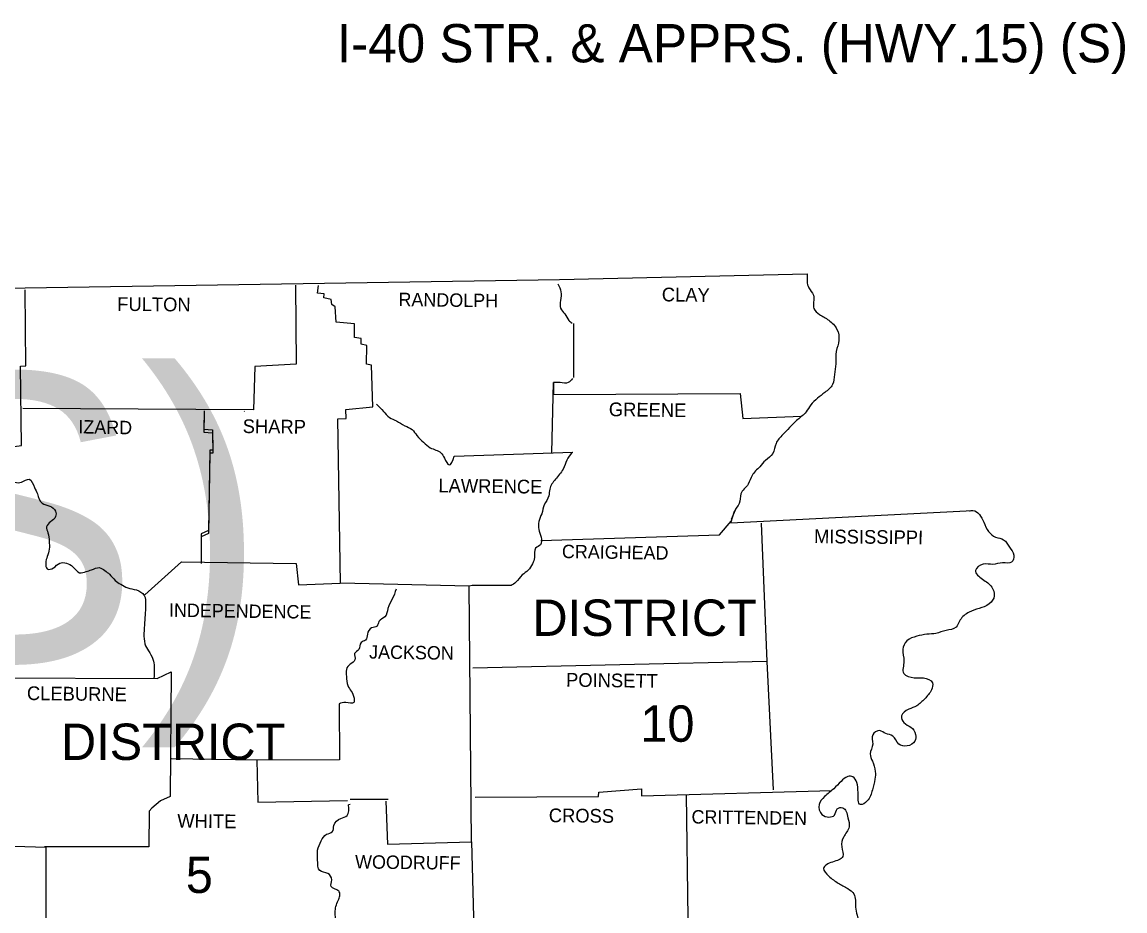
# Model space of a CAD drawing. Extents: x 1127717 to 1741049, y 2026793 to 2244711.
# Drawn here: x 1371845 to 1389121, y 2139792 to 2153727 of the extents above; entities that cross this region are included whole.
import ezdxf

# ---------------------------------------------------------------- set-up
doc = ezdxf.new("R2010")
doc.units = 0
doc.layers.add('1', color=7, linetype='Continuous')
doc.layers.add('R_Draft', color=7, linetype='Continuous')

msp = doc.modelspace()

# ---------------------------------------------------------------- linework, layer by layer
at = {"layer": 'R_Draft'}
for p, q in [((1380455, 2146979), (1380470, 2146984)), ((1382945, 2145874), (1383005, 2146059)), ((1382960, 2145934), (1383020, 2146079)), ((1376985, 2141544), (1377580, 2141544))]:
    msp.add_line(p, q, dxfattribs=at)
for points in [[(1356715, 2149549), (1364800, 2149544), (1371895, 2149559), (1380265, 2149689), (1384145, 2149779)], [(1370380, 2137464), (1371505, 2137469), (1371555, 2138059), (1372225, 2138109), (1372225, 2140789), (1371375, 2140814), (1371390, 2143449), (1370320, 2143519), (1370305, 2144699), (1370270, 2144759), (1370300, 2145499), (1370920, 2145519), (1370945, 2146129), (1371625, 2146154), (1371635, 2146549), (1371515, 2146704), (1371485, 2147039), (1371835, 2147089), (1371820, 2148334), (1371905, 2148339), (1371895, 2149529)], [(1376130, 2149604), (1376140, 2148364), (1375490, 2148329), (1375470, 2147649), (1371855, 2147669)], [(1377545, 2141514), (1377570, 2140839), (1378885, 2140874), (1378850, 2144884), (1376835, 2144929), (1376790, 2147509), (1376920, 2147514), (1376915, 2147654), (1377340, 2147694), (1377320, 2148349), (1377240, 2148364), (1377245, 2148654), (1377155, 2148679), (1377155, 2148764), (1377050, 2148779), (1377050, 2148994), (1376765, 2149024), (1376750, 2149264), (1376695, 2149299), (1376685, 2149379), (1376570, 2149404), (1376575, 2149464), (1376475, 2149479), (1376490, 2149599)], [(1380485, 2148999), (1380485, 2148154)], [(1380143, 2146973), (1380170, 2148074), (1380170, 2147889), (1383095, 2147904), (1383135, 2147514), (1384053, 2147548)], [(1374700, 2147634), (1374690, 2147344), (1374830, 2147334), (1374835, 2147014), (1374785, 2147014), (1374765, 2145754), (1374650, 2145704), (1374650, 2145284)], [(1375325, 2147624), (1375330, 2147629)], [(1374700, 2147589), (1374690, 2147299), (1374830, 2147289), (1374835, 2146969), (1374785, 2146969), (1374765, 2145709), (1374650, 2145659), (1374650, 2145239)], [(1378615, 2146919), (1380470, 2146984)], [(1382945, 2145874), (1386740, 2146069)], [(1379970, 2145599), (1382770, 2145689), (1382953, 2145901)], [(1383425, 2145869), (1383510, 2143704), (1383610, 2141689)], [(1373770, 2144749), (1374340, 2145264), (1376140, 2145239), (1376175, 2144904), (1376830, 2144929)], [(1379505, 2144894), (1378895, 2144894), (1378850, 2144884)], [(1383510, 2143704), (1378905, 2143599)], [(1371390, 2143449), (1373960, 2143434), (1374180, 2143539), (1374165, 2141584), (1374015, 2141519), (1373880, 2141404), (1373835, 2141359), (1373830, 2140799), (1372195, 2140799)], [(1376810, 2143039), (1376820, 2142159), (1375520, 2142154), (1374185, 2142179)], [(1375520, 2142154), (1375540, 2141499), (1376945, 2141524)], [(1378945, 2141574), (1380875, 2141584), (1380880, 2141654), (1381550, 2141704), (1381550, 2141599), (1384528, 2141681)], [(1382249, 2141619), (1382275, 2139674), (1382320, 2139644), (1382336, 2139368)], [(1376985, 2141459), (1376960, 2141454)], [(1378885, 2140874), (1378960, 2138134), (1377770, 2138129), (1377765, 2138019), (1377420, 2137999), (1377390, 2137429), (1376970, 2137429)]]:
    msp.add_lwpolyline(points, dxfattribs=at)
for points in [[(1384145, 2149779), (1384170, 2149559), (1384240, 2149444), (1384250, 2149234), (1384335, 2149144), (1384480, 2149054), (1384610, 2148909), (1384640, 2148739), (1384600, 2148564), (1384590, 2148369), (1384570, 2148199), (1384540, 2148044), (1384420, 2147919), (1384305, 2147829), (1384200, 2147724), (1384125, 2147614), (1383995, 2147494), (1383865, 2147369), (1383760, 2147259), (1383655, 2147119), (1383605, 2146964), (1383490, 2146854), (1383400, 2146754), (1383280, 2146619), (1383220, 2146484), (1383105, 2146329), (1383080, 2146179), (1383005, 2146059), (1383000, 2146039)], [(1384145, 2149779), (1384170, 2149559), (1384240, 2149444), (1384250, 2149234), (1384335, 2149144), (1384480, 2149054), (1384610, 2148909), (1384640, 2148739), (1384600, 2148564), (1384590, 2148369), (1384570, 2148199), (1384540, 2148044), (1384420, 2147919), (1384305, 2147829), (1384200, 2147724), (1384125, 2147614), (1383995, 2147494), (1383865, 2147369), (1383760, 2147259), (1383655, 2147119), (1383605, 2146964), (1383490, 2146854), (1383400, 2146754), (1383280, 2146619), (1383220, 2146484), (1383105, 2146329), (1383080, 2146179), (1383005, 2146059), (1383000, 2146039)], [(1380240, 2149624), (1380285, 2149499), (1380280, 2149364), (1380280, 2149239), (1380345, 2149154), (1380410, 2149049), (1380460, 2149004)], [(1380465, 2148139), (1380400, 2148074), (1380275, 2148074), (1380170, 2148074)], [(1377395, 2147739), (1377505, 2147624), (1377600, 2147529), (1377710, 2147474), (1377840, 2147399), (1377955, 2147339), (1378030, 2147244), (1378135, 2147139), (1378240, 2147054), (1378405, 2146974), (1378460, 2146889), (1378535, 2146784), (1378615, 2146919)], [(1380455, 2146979), (1380380, 2146859), (1380320, 2146719), (1380200, 2146559), (1380110, 2146404), (1380095, 2146299), (1380025, 2146159), (1379985, 2146019), (1379940, 2145899), (1379940, 2145774), (1379975, 2145649), (1379965, 2145534), (1379890, 2145479), (1379870, 2145334), (1379840, 2145234), (1379775, 2145134), (1379680, 2145059), (1379580, 2144944), (1379505, 2144894)], [(1371635, 2146549), (1371835, 2146514), (1371955, 2146559), (1372040, 2146429), (1372085, 2146329), (1372160, 2146184), (1372280, 2146139), (1372370, 2146059), (1372370, 2145974), (1372290, 2145894), (1372230, 2145814), (1372250, 2145719), (1372270, 2145589), (1372270, 2145464), (1372240, 2145349), (1372215, 2145244), (1372240, 2145154), (1372335, 2145169), (1372435, 2145244), (1372540, 2145244), (1372640, 2145189), (1372745, 2145094), (1372850, 2145114), (1372935, 2145139), (1373055, 2145174), (1373140, 2145129), (1373215, 2145069), (1373305, 2144974), (1373390, 2144914), (1373500, 2144859), (1373635, 2144824), (1373760, 2144739), (1373780, 2144594), (1373775, 2144469), (1373765, 2144314), (1373755, 2144144), (1373770, 2143979), (1373825, 2143869), (1373895, 2143739), (1373915, 2143619), (1373910, 2143429)], [(1386685, 2146064), (1386740, 2146069), (1386910, 2145889), (1386985, 2145739), (1387095, 2145654), (1387220, 2145609), (1387315, 2145494), (1387380, 2145369), (1387345, 2145259), (1387205, 2145249), (1387050, 2145224), (1386900, 2145229), (1386780, 2145129), (1386890, 2144994), (1387035, 2144869), (1387075, 2144734), (1386995, 2144604), (1386835, 2144534), (1386680, 2144474), (1386540, 2144354), (1386475, 2144239), (1386320, 2144189), (1386160, 2144144), (1386020, 2144129), (1385860, 2144099), (1385705, 2144024), (1385640, 2143894), (1385660, 2143709), (1385655, 2143514), (1385820, 2143449), (1385965, 2143444), (1386105, 2143369), (1386090, 2143259), (1385985, 2143119), (1385860, 2143009), (1385735, 2142954), (1385620, 2142849), (1385660, 2142744), (1385765, 2142674), (1385840, 2142559), (1385830, 2142454), (1385710, 2142379), (1385580, 2142409), (1385485, 2142534), (1385375, 2142574), (1385280, 2142619), (1385170, 2142554), (1385170, 2142409), (1385130, 2142254), (1385165, 2142139), (1385210, 2141979), (1385205, 2141859), (1385165, 2141689), (1385080, 2141514), (1384980, 2141459), (1384940, 2141649), (1384920, 2141804), (1384860, 2141894), (1384780, 2141899), (1384675, 2141824), (1384560, 2141709), (1384415, 2141584), (1384330, 2141459), (1384375, 2141304), (1384485, 2141264), (1384570, 2141294), (1384615, 2141394), (1384700, 2141409), (1384780, 2141254)], [(1386685, 2146064), (1386740, 2146069), (1386910, 2145889), (1386985, 2145739), (1387095, 2145654), (1387220, 2145609), (1387315, 2145494), (1387380, 2145369), (1387345, 2145259), (1387205, 2145249), (1387050, 2145224), (1386900, 2145229), (1386780, 2145129), (1386890, 2144994), (1387035, 2144869), (1387075, 2144734), (1386995, 2144604), (1386835, 2144534), (1386680, 2144474), (1386540, 2144354), (1386475, 2144239), (1386320, 2144189), (1386160, 2144144), (1386020, 2144129), (1385860, 2144099), (1385705, 2144024), (1385640, 2143894), (1385660, 2143709), (1385655, 2143514), (1385820, 2143449), (1385965, 2143444), (1386105, 2143369), (1386090, 2143259), (1385985, 2143119), (1385860, 2143009), (1385735, 2142954), (1385620, 2142849), (1385660, 2142744), (1385765, 2142674), (1385840, 2142559), (1385830, 2142454), (1385710, 2142379), (1385580, 2142409), (1385485, 2142534), (1385375, 2142574), (1385280, 2142619), (1385170, 2142554), (1385170, 2142409), (1385130, 2142254), (1385165, 2142139), (1385210, 2141979), (1385205, 2141859), (1385165, 2141689), (1385080, 2141514), (1384980, 2141459), (1384940, 2141649), (1384920, 2141804), (1384860, 2141894), (1384780, 2141899), (1384675, 2141824), (1384560, 2141709), (1384415, 2141584), (1384330, 2141459), (1384375, 2141304), (1384485, 2141264), (1384570, 2141294), (1384615, 2141394), (1384700, 2141409), (1384780, 2141254)], [(1377705, 2144839), (1377645, 2144684), (1377575, 2144534), (1377530, 2144404), (1377435, 2144329), (1377405, 2144259), (1377320, 2144229), (1377255, 2144129), (1377225, 2144039), (1377155, 2143999), (1377120, 2143889), (1377055, 2143829), (1377060, 2143729), (1376985, 2143659), (1376925, 2143579), (1376925, 2143469), (1376950, 2143324), (1377000, 2143239), (1377045, 2143129), (1377040, 2143059), (1376915, 2143059), (1376810, 2143039)], [(1376350, 2138469), (1376325, 2138504), (1376355, 2138614), (1376370, 2138684), (1376320, 2138784), (1376365, 2138869), (1376415, 2138959), (1376430, 2139064), (1376470, 2139134), (1376455, 2139224), (1376475, 2139349), (1376530, 2139444), (1376610, 2139579), (1376745, 2139614), (1376755, 2139669), (1376750, 2139794), (1376805, 2139979), (1376825, 2140044), (1376805, 2140104), (1376685, 2140174), (1376695, 2140279), (1376635, 2140379), (1376510, 2140424), (1376475, 2140594), (1376475, 2140744), (1376530, 2140889), (1376615, 2140994), (1376705, 2141034), (1376730, 2141134), (1376840, 2141244), (1376935, 2141289), (1376960, 2141454)], [(1384780, 2141254), (1384800, 2141109), (1384715, 2140954), (1384685, 2140799), (1384700, 2140644), (1384540, 2140559), (1384400, 2140459), (1384480, 2140339), (1384630, 2140229), (1384780, 2140144), (1384875, 2140059), (1384900, 2139854), (1384925, 2139724), (1384975, 2139544), (1384995, 2139419), (1384905, 2139269), (1384800, 2139239), (1384690, 2139274), (1384560, 2139284), (1384455, 2139184), (1384380, 2139044), (1384305, 2138904), (1384250, 2138784), (1384195, 2138654), (1384085, 2138504), (1383950, 2138479), (1383790, 2138439), (1383695, 2138329), (1383710, 2138144), (1383800, 2138019), (1383870, 2137864), (1383920, 2137729), (1383895, 2137559), (1383825, 2137434), (1383735, 2137359), (1383695, 2137199), (1383630, 2137079), (1383570, 2137039), (1383450, 2137049), (1383320, 2137074), (1383210, 2137064), (1383105, 2137009), (1383000, 2137044), (1382890, 2137164), (1382800, 2137254), (1382700, 2137289), (1382595, 2137234), (1382575, 2137069), (1382625, 2136899), (1382670, 2136669), (1382625, 2136529), (1382610, 2136299)], [(1384780, 2141254), (1384800, 2141109), (1384715, 2140954), (1384685, 2140799), (1384700, 2140644), (1384540, 2140559), (1384400, 2140459), (1384480, 2140339), (1384630, 2140229), (1384780, 2140144), (1384875, 2140059), (1384900, 2139854), (1384925, 2139724), (1384975, 2139544), (1384995, 2139419), (1384905, 2139269), (1384800, 2139239), (1384690, 2139274), (1384560, 2139284), (1384455, 2139184), (1384380, 2139044), (1384305, 2138904), (1384250, 2138784), (1384195, 2138654), (1384085, 2138504), (1383950, 2138479), (1383790, 2138439), (1383695, 2138329), (1383710, 2138144), (1383800, 2138019), (1383870, 2137864), (1383920, 2137729), (1383895, 2137559), (1383825, 2137434), (1383735, 2137359), (1383695, 2137199), (1383630, 2137079), (1383570, 2137039), (1383450, 2137049), (1383320, 2137074), (1383210, 2137064), (1383105, 2137009), (1383000, 2137044), (1382890, 2137164), (1382800, 2137254), (1382700, 2137289), (1382595, 2137234), (1382575, 2137069), (1382625, 2136899), (1382670, 2136669), (1382625, 2136529), (1382610, 2136299)]]:
    msp.add_spline(points, degree=3, dxfattribs=at)

# ---------------------------------------------------------------- texts
at = {"layer": '1'}
msp.add_text('I-40 STR. & APPRS. (HWY.15) (S)', height=600, dxfattribs=at).set_placement((1376777, 2153095))
at = {"layer": 'R_Draft'}
for s, height, rotation, p in [('CLAY', 215, 359.2258, (1381865, 2149349)), ('FULTON', 215, 359.4996, (1373335, 2149199)), ('RANDOLPH', 210, 359.2583, (1377740, 2149274)), ('GREENE', 215, 359.2361, (1381035, 2147549)), ('IZARD', 210, 358.9258, (1372725, 2147279)), ('SHARP', 215, 359.3905, (1375300, 2147284)), ('LAWRENCE', 215, 359.2678, (1378365, 2146354)), ('MISSISSIPPI', 214.98, 359.3097, (1384250, 2145559)), ('CRAIGHEAD', 210, 359.1159, (1380300, 2145324)), ('INDEPENDENCE', 209.97, 359.2187, (1374145, 2144404)), ('JACKSON', 210, 359.1352, (1377280, 2143749)), ('POINSETT', 215, 359.1987, (1380365, 2143309)), ('CLEBURNE', 215, 359.2535, (1371920, 2143099)), ('CROSS', 215, 359.3839, (1380095, 2141184)), ('CRITTENDEN', 210, 359.213, (1382330, 2141164)), ('WHITE', 215, 359.3139, (1374275, 2141099)), ('WOODRUFF', 210, 359.2748, (1377060, 2140459))]:
    msp.add_text(s, height=height, rotation=rotation, dxfattribs=at).set_placement(p)
for s, height, p in [('I-40 STR. & APPRS. (HWY. 15) (S)', 4500, (1281068, 2143713)), ('DISTRICT', 570, (1379840, 2144104)), ('10', 570, (1381530, 2142444)), ('DISTRICT', 570, (1372455, 2142159)), ('5', 570, (1374410, 2140074))]:
    msp.add_text(s, height=height, dxfattribs=at).set_placement(p)

doc.saveas('drawing.dxf')
